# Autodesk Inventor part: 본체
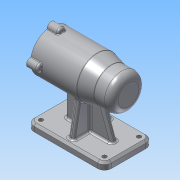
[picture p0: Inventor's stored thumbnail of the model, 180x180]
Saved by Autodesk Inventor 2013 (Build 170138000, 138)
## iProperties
Created: 2019-07
Part Number: 본체
Material: 알루미늄 6061
Document SubType Name: Modeling
Designer: Administrator
Density: 2.71 g/cm^3
Mass: 645.295 g
Surface Area: 654.416 cm^2
Volume: 238.116 cm^3
Author: Administrator
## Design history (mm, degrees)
sketch "스케치1"
  geometry: L1 (-46, 35)-(46, 35); L2 (56, 25)-(56, -25); L3 (46, -35)-(-46, -35); L4 (-56, -25)-(-56, 25); A1 r 10 centre (-46, 25) between (-46, 35) and (-56, 25); A2 r 10 centre (-46, -25) between (-56, -25) and (-46, -35); A3 r 10 centre (46, -25) between (46, -35) and (56, -25); A4 r 10 centre (46, 25) between (56, 25) and (46, 35); 7 further points
  constraints: 8 end point, 8 point on circle, 8 point on line, 8 tangent, 4 centre point, 3 equal radius, 2 midpoint, 2 parallel, 1 horizontal, 1 horizontal alignment, 1 perpendicular, 1 vertical alignment
  dimensions: "d0" = 112 distance of point (-56, 35) point (56, 35); "d2" = 70 distance of point (56, 35) point (56, -35); "d5" = 10 radius of A1
extrude "돌출1" new body sketch "스케치1" distance "d3" = 10; taper "d4" = 0 deg
sketch "스케치2"
  geometry: L1 (-56, 80)-(56, 80); L2 (-56, 105)-(-56, 80); L3 (-56, 105)-(-31, 105); L4 (-31, 105)-(-11, 110); L5 (-11, 110)-(56, 110); L6 (56, 110)-(56, 80); 3 further points
  constraints: 12 end point, 2 vertical alignment, 1 horizontal, 1 midpoint, 1 parallel, 1 perpendicular, 1 vertical
  dimensions: "d6" = 80 vertical distance of L1.end point (0, 0); "d7" = 60 diameter of L5 L1; "d8" = 50 diameter of L3 L1; "d9" = 45 distance from line of L4.end L2; "d10" = 25 distance of L3.end L2.start
revolve "회전1" sketch "스케치2" stored, may be unused: angle "d11" = 90 deg
sketch "스케치3"
  geometry: L1 (-56, 80)-(56, 80); L2 (-56, 55)-(-56, 105) reference; L3 (56, 50)-(56, 110) reference; L4 (-50, 80)-(-50, 90.5); L5 (-50, 90.5)-(-47, 90.5); L6 (-47, 90.5)-(-47, 96); L7 (-47, 96)-(-43, 96); L8 (-43, 96)-(-43, 97.5); L9 (-43, 97.5)-(-25, 97.5); L10 (-25, 97.5)-(-25, 101); L11 (-11, 50)-(-11, 110) reference; L12 (-25, 101)-(-13, 101); L13 (-13, 101)-(-13, 104); L14 (-13, 104)-(41, 104); L15 (41, 104)-(41, 101); L16 (41, 101)-(56, 101); 1 further point
  constraints: 26 end point, 8 parallel, 3 perpendicular, 2 midpoint, 2 point on line, 1 collinear, 1 horizontal
  dimensions: "d12" = 80 vertical distance of point (0, 0) L1.end; "d13" = 21 diameter of L5 L1; "d14" = 32 diameter of L7 L1; "d15" = 35 diameter of L9 L1; "d16" = 42 diameter of L16 L1; "d17" = 3 distance of L4.end L5.end; "d18" = 4 distance of L6.end L7.end; "d19" = 18 distance of L8.end L9.end; "d20" = 12 distance of L10.end L12.end; "d21" = 48 diameter of L14 L1; "d22" = 54 distance of L13.end L14.end; "d23" = 15 distance of L15.end L16.end; "d24" = 42 diameter of L12 L1
revolve "회전2" sketch "스케치3" stored, may be unused: angle "d25" = 90 deg
sketch "스케치4"
  geometry: L1 (-56, 25)-(-56, -25) reference; L2 (0, 4)-(-31, 4); L3 (-31, 4)-(-31, -4); L4 (-31, -4)-(0, -4); L5 (0, -4)-(0, 4); 2 further points
  constraints: 8 end point, 2 parallel, 1 coincident, 1 horizontal, 1 midpoint, 1 perpendicular
  dimensions: "d26" = 8 distance of L4.end L2.start; "d28" = 25 distance between parallel lines of L1 L3
extrude "돌출2" join sketch "스케치4" stored distance "d29" = 10; taper "d30" = 0 deg
sketch "스케치5"
  geometry: L1 (46, 10)-(-46, 10) reference; L2 (-36, 10)-(-20.57, 52.393); L3 (-56, 0)-(-56, 10) reference; L4 (-46, 10)-(-56, 10) reference; L5 (-31, 55)-(-11, 50) reference; 1 further point
  constraints: 2 end point, 2 point on line
  dimensions: "d31" = 20 distance from line of L2.start L3; "d32" = 110 deg angle of L2 L4
feature "리브1" sketch "스케치5" dims "d33" = 1, "d34" = 8, "d35" = 0, "d36" = 0, "d37" = 1, "d38" = 1
sketch "스케치6"
  geometry: L1 (-25, 10)-(-35, 10) reference; L2 (-28, 10)-(-19.654, 57.334); L3 (-35, 0)-(-35, 10) reference; 2 further points
  constraints: 2 end point, 1 point on line, 2 other
  dimensions: "d55" = 7 distance from line of L2.start L3; "d56" = 100 deg angle of L2 L1
feature "리브2" sketch "스케치6" dims "d40" = 1, "d41" = 8, "d42" = 0, "d43" = 0, "d44" = 1, "d45" = 1
sketch "스케치7"
  geometry: L1 (25, 10)-(-25, 10) reference; L2 (28, 10)-(19.654, 57.334); L3 (35, 10)-(25, 10) reference; L4 (35, 0)-(35, 10) reference; 2 further points
  constraints: 2 end point, 1 point on line, 2 other
  dimensions: "d46" = 100 deg angle of L2 L3; "d48" = 7 distance from line of L2.start L4
feature "리브3" sketch "스케치7" dims "d49" = 1, "d50" = 8, "d51" = 0, "d52" = 0, "d53" = 1, "d54" = 1
sketch "스케치8"
  geometry: C1 r 6 at (30, 0); 2 further points
  constraints: 2 horizontal alignment, 1 centre point, 1 other
  dimensions: "d57" = 12 diameter of C1
extrude "돌출3" join sketch "스케치8" distance "d60" = 16; taper "d61" = 0 deg
sketch "스케치9"
  geometry: A1 r 6 centre (0, 0) between (-0.6, -5.97) and (-0.6, 5.97) reference; 2 further points
  constraints: 1 coincident
hole "구멍1" sketch "스케치9" at (0, 0) diameter "d62" = 3.242; stored, may be unused: countersink angle "d66" = 90 deg, drill point angle "d68" = 118 deg; dims "d63" = 8, "d64" = 4, "d65" = 2, "d67" = 11
sketch "스케치10"
  geometry: C1 r 3 at (46, 25); C2 r 3 at (-46, 25); C3 r 3 at (-46, -25); C4 r 3 at (46, -25); A1 r 10 centre (46, 25) between (56, 25) and (46, 35) reference; A2 r 10 centre (46, -25) between (46, -35) and (56, -25) reference; A3 r 10 centre (-46, 25) between (-46, 35) and (-56, 25) reference; A4 r 10 centre (-46, -25) between (-56, -25) and (-46, -35) reference; 1 further point
  constraints: 4 centre point, 4 coincident, 3 equal radius
  dimensions: "d72" = 6 diameter of C1
extrude "돌출4" cut sketch "스케치10" distance "d74" = 16; taper "d75" = 0 deg
node "작업 평면1"
sketch "스케치11"
  geometry: L1 (33.5, -29.4)-(33.5, -5.97) reference; L2 (23.5, -80)-(-68.5, -80) reference; 2 further points
  constraints: 1 other
  dimensions: "d76" = 42 distance from line of L1 point (-8.5, 0); "d77" = 80 distance from line of L2 point (-8.5, 0)
feature "엠보싱1" sketch "스케치11" dims "d0" = 112, "d2" = 70, "d5" = 10, "d78" = 0.5, "d79" = 0
fillet "모깎기1" dims "d80" = 0.3
fillet "모깎기2" dims "d81" = 10
fillet "모깎기4" dims "d83" = 3
fillet "모깎기6" dims "d85" = 3
chamfer "모따기1" distance "d86" = 3; stored, may be unused: second distance "d87" = 2, angle "d88" = 45 deg
chamfer "모따기2" distance "d89" = 1; stored, may be unused: second distance "d90" = 2, angle "d91" = 45 deg
fillet "모깎기7" dims "d92" = 3
fillet "모깎기8" dims "d93" = 1
fillet "모깎기9" dims "d94" = 3
fillet "모깎기10" dims "d95" = 3
fillet "모깎기11" dims "d96" = 3
fillet "모깎기12" dims "d97" = 3
node "솔리드1"
pattern_circular "원형 패턴1" dims angle "d70" = 360 deg
